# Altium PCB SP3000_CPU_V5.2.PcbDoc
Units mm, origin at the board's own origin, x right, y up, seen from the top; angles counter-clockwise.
Board outline 91.48 x 91.59 mm, 4 copper layers (Top Layer, PWR, GND, Bottom Layer); 84 components, 93 nets, 328 pads, 88 vias.
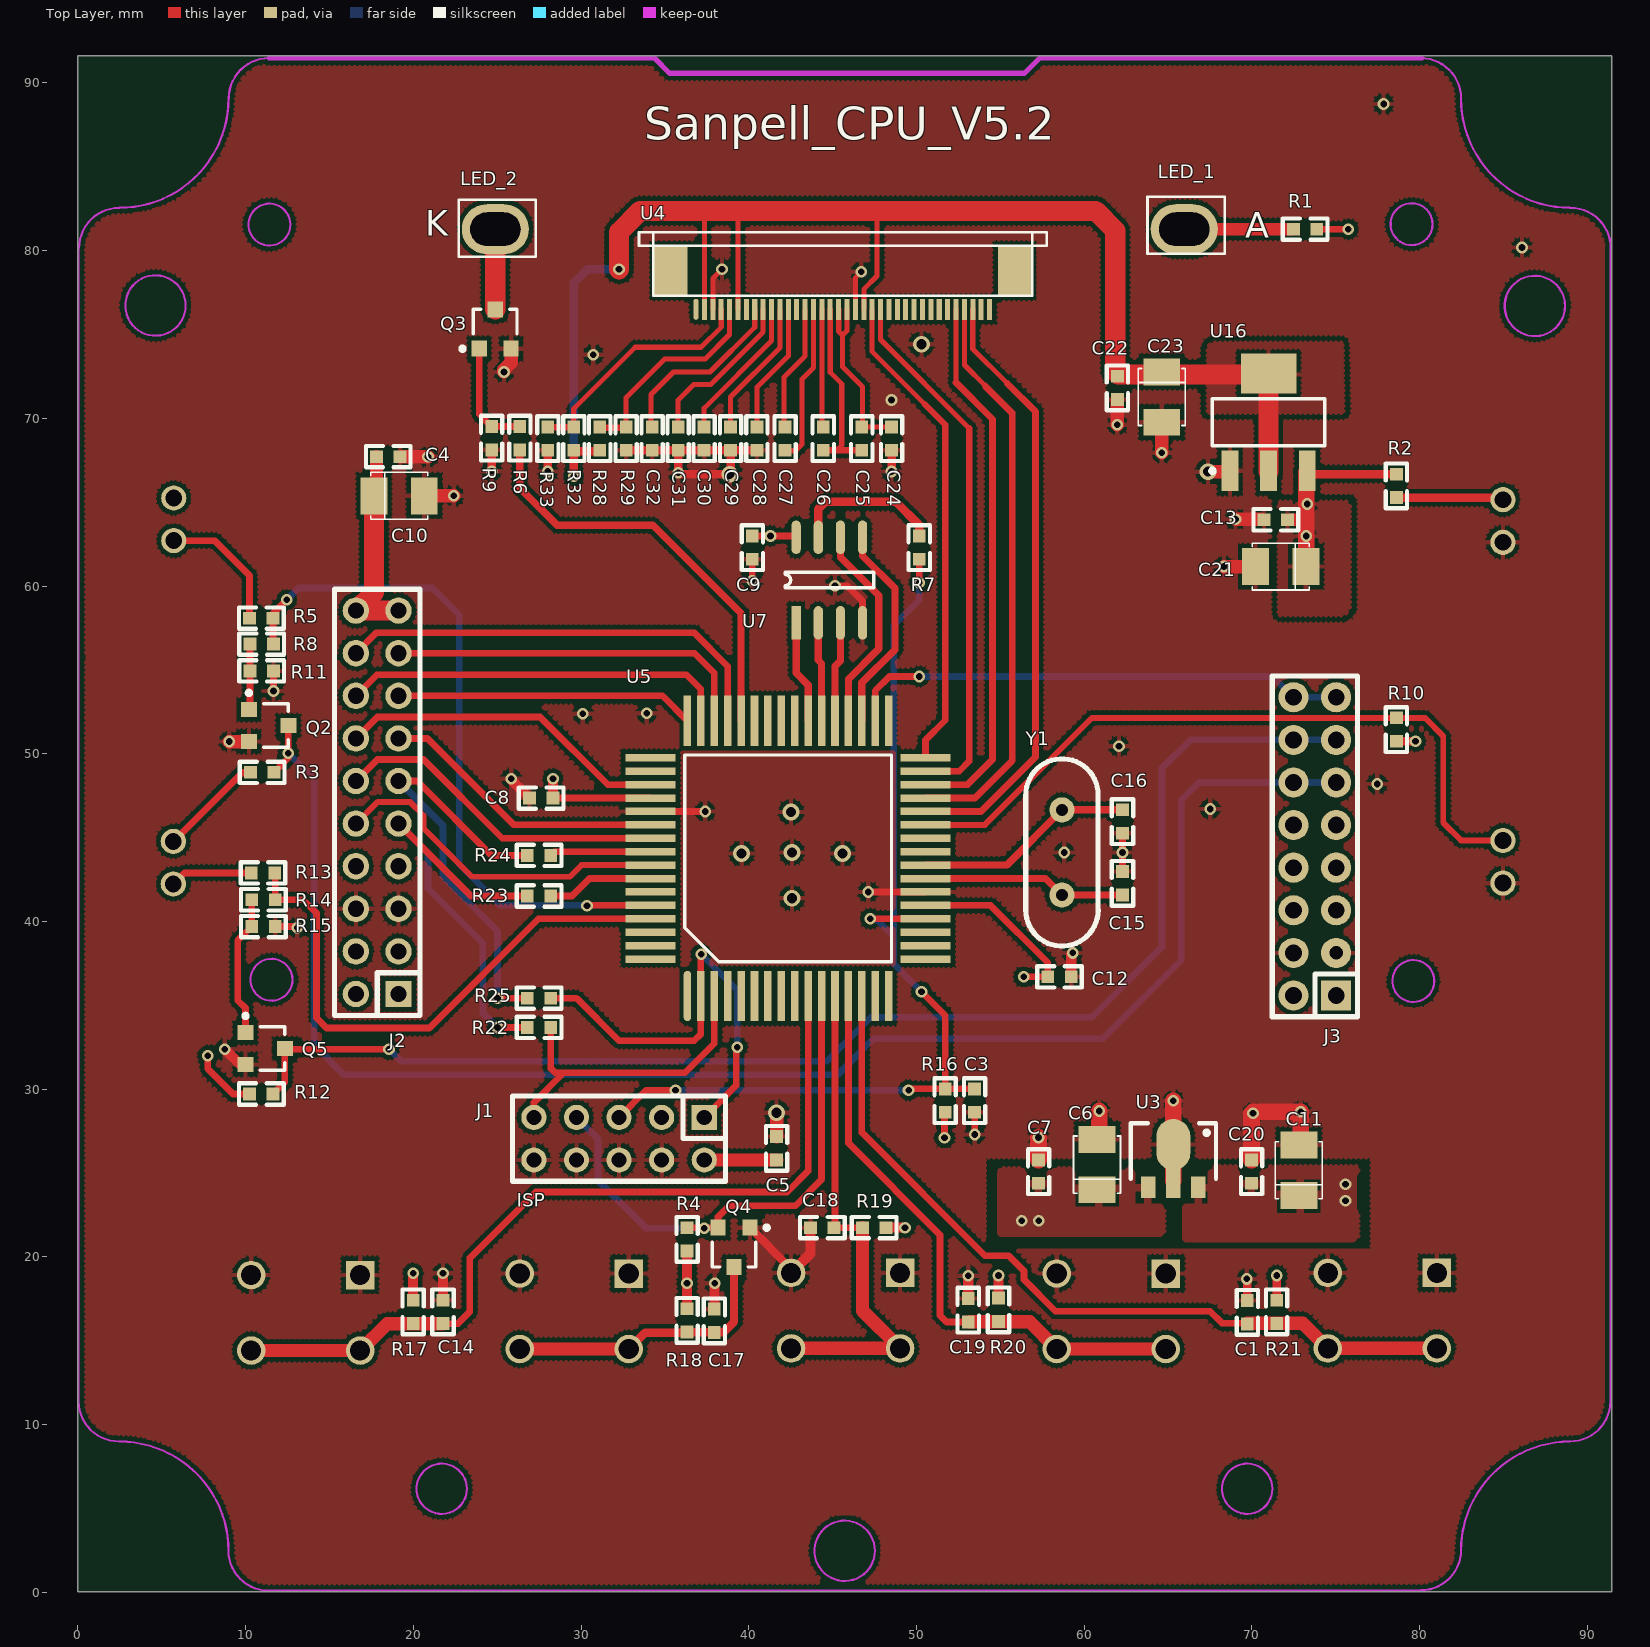
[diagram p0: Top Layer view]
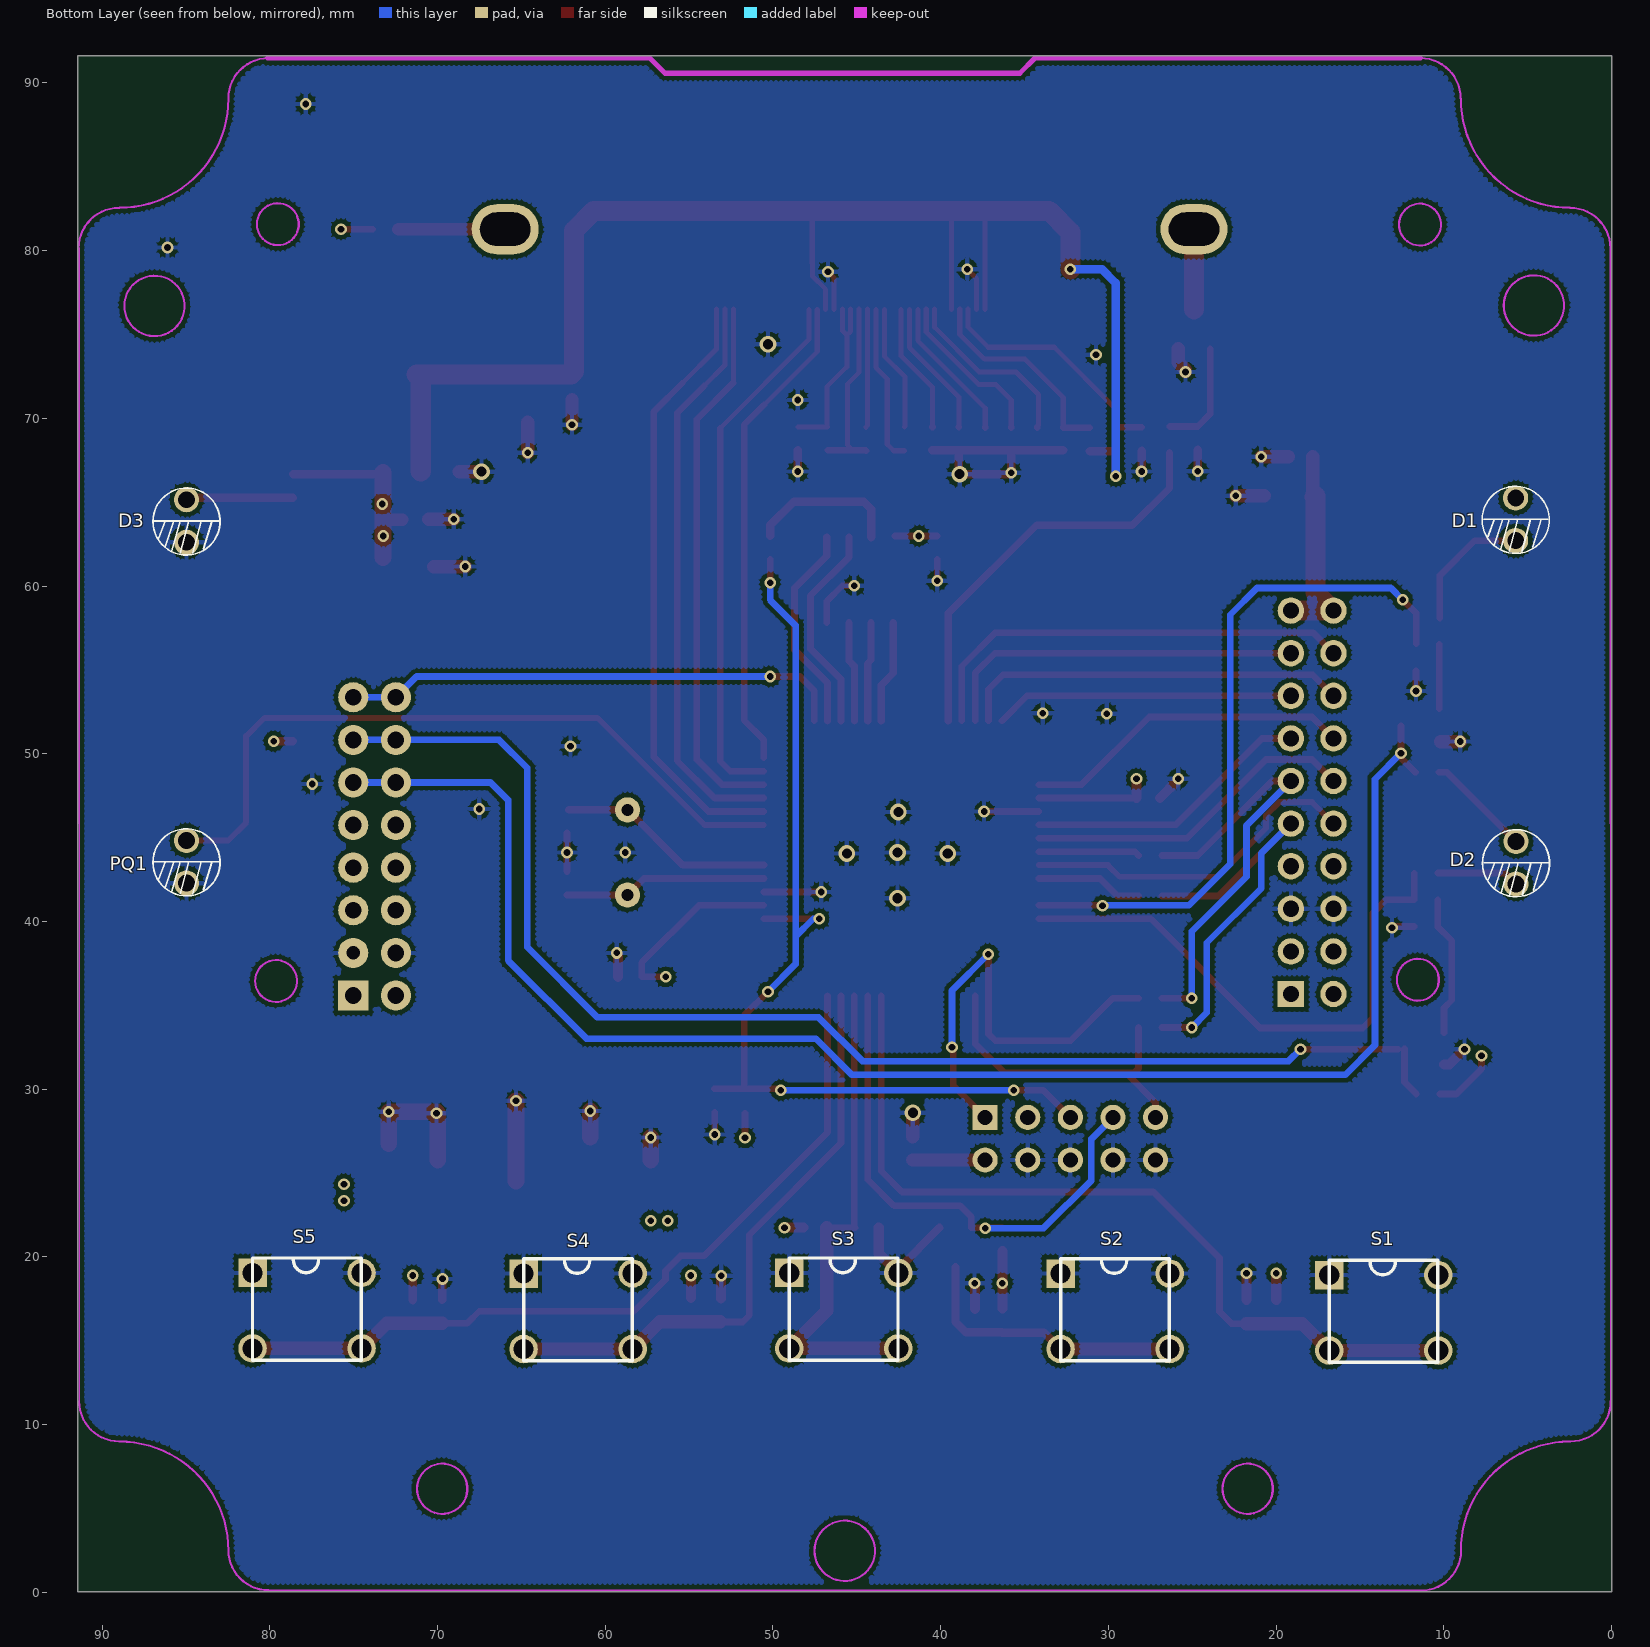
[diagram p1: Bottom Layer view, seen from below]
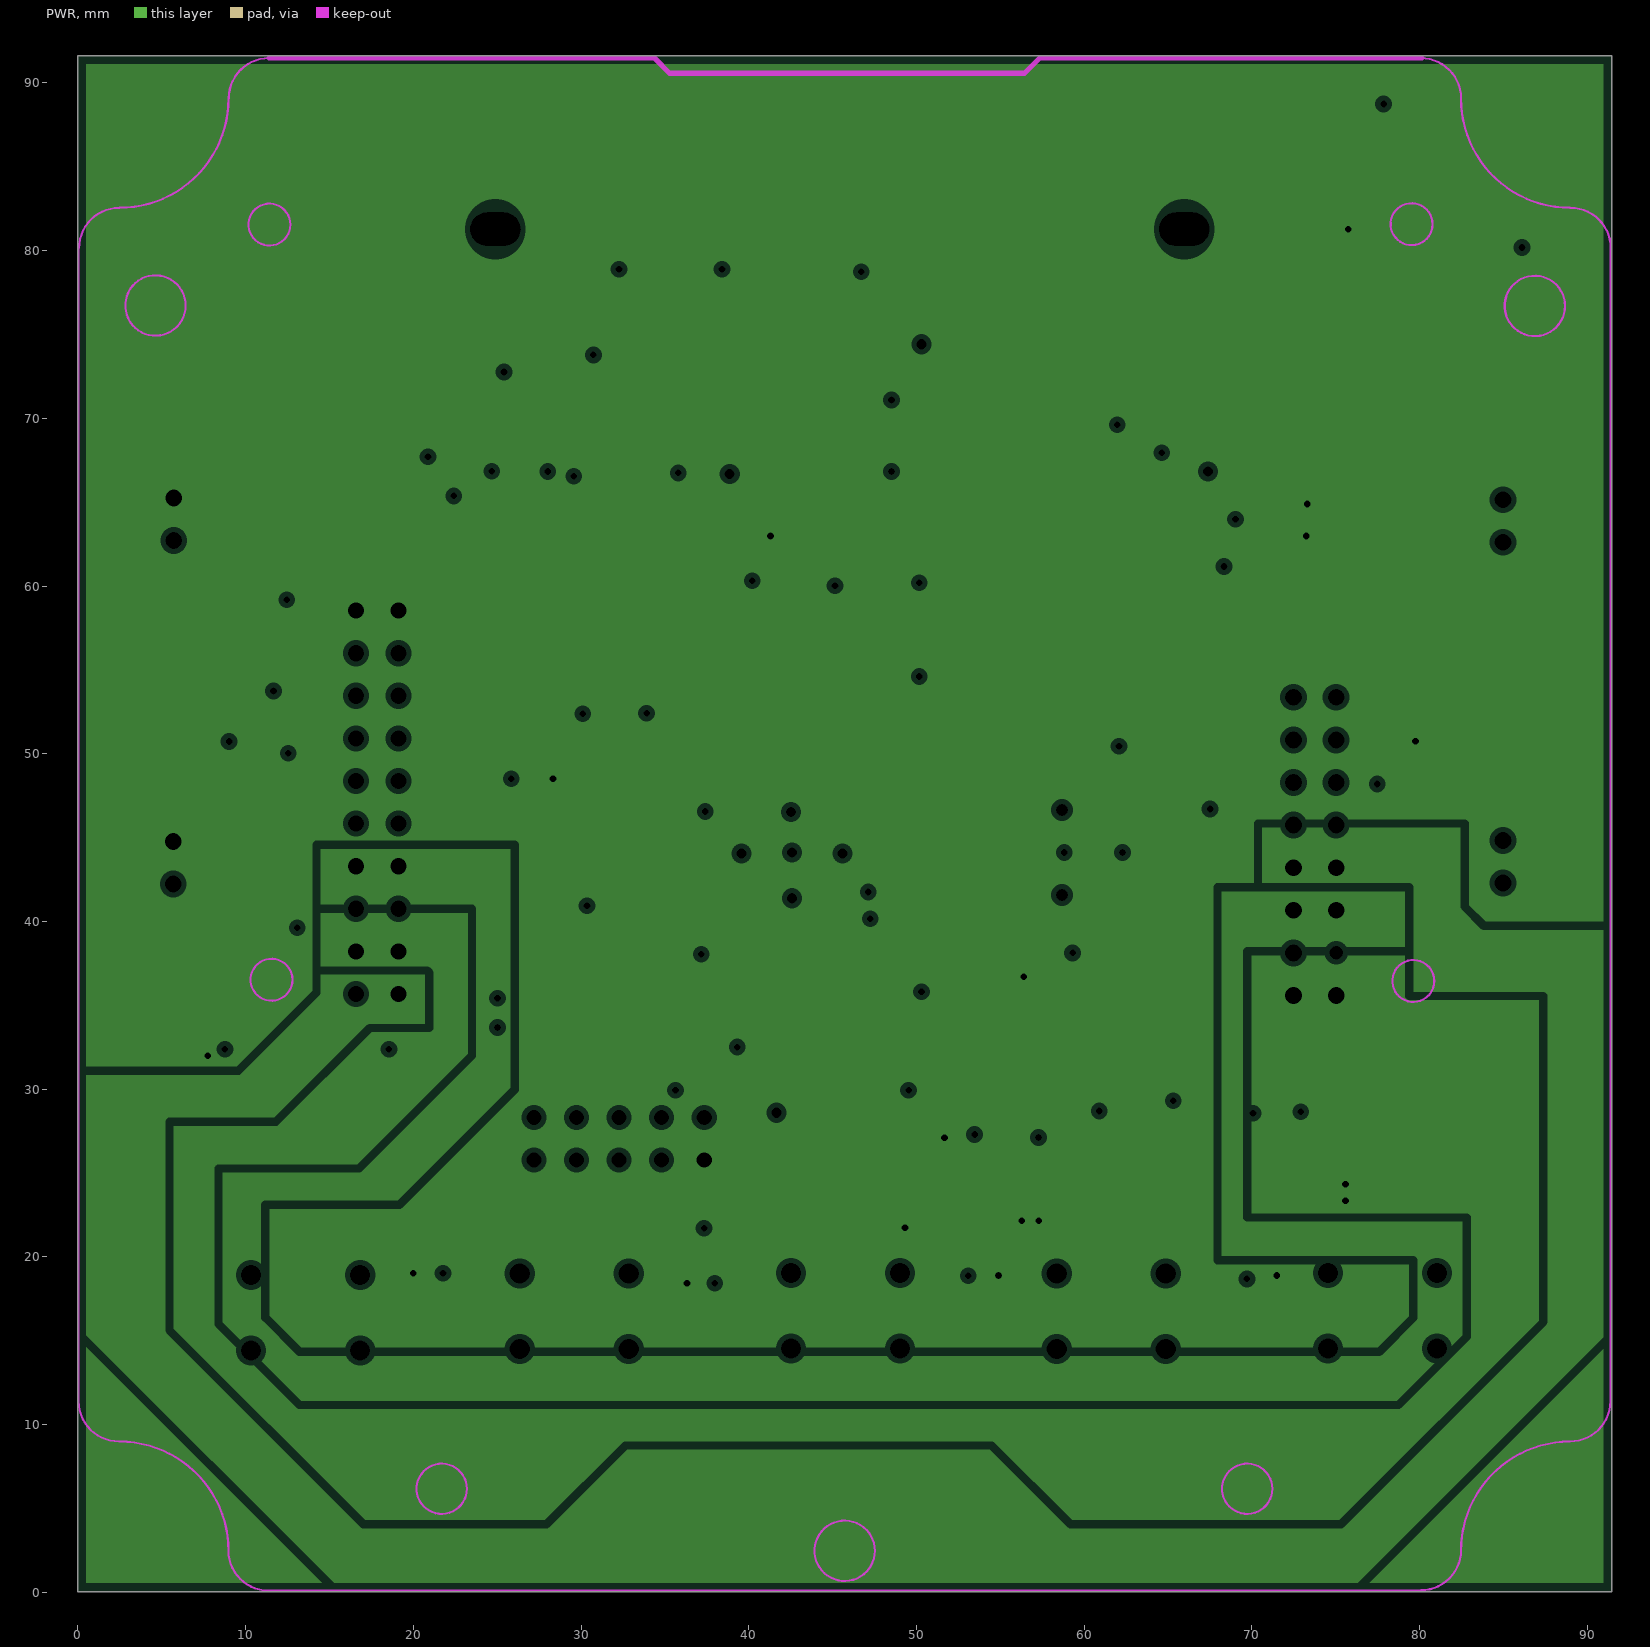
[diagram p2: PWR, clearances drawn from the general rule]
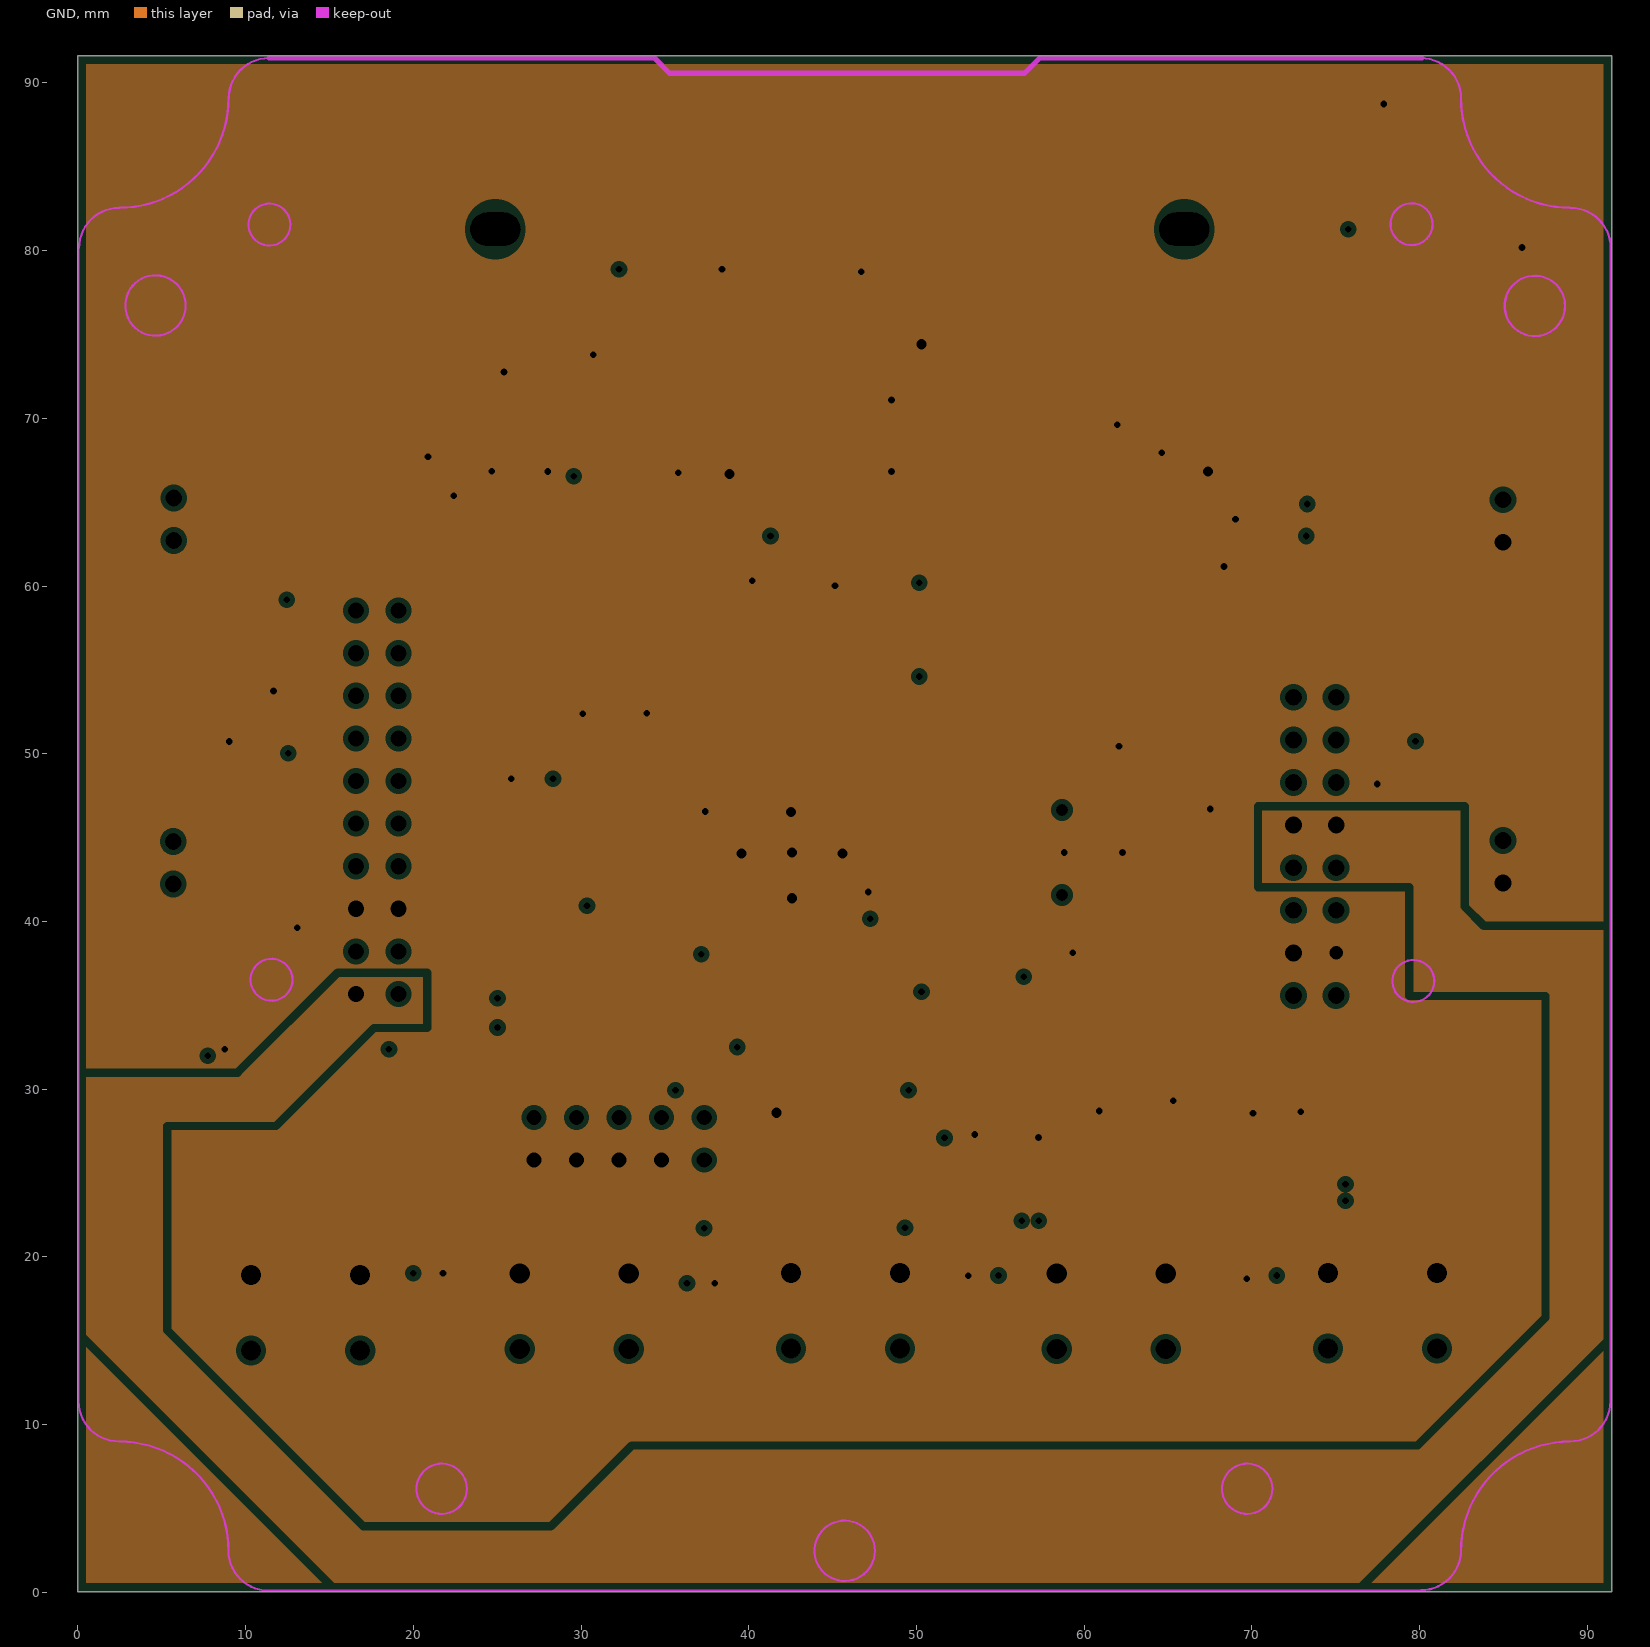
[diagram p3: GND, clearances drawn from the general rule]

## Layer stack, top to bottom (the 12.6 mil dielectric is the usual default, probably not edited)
Top Layer: signal copper 0.0356
Dielectric: prepreg 0.32, FR-4, Dk 4.8
PWR: plane copper 0.0356, net (Multiple Nets)
Dielectric: core 0.32, FR-4, Dk 4.8
GND: plane copper 0.0356, net (Multiple Nets)
Dielectric: prepreg 0.32, FR-4, Dk 4.8
Bottom Layer: signal copper 0.0356

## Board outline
-0.02,0.041 91.457,0.041 91.457,91.632 -0.02,91.632

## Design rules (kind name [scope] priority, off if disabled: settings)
Clearance Clearance_poly [InPolygon] p1: gap=0.254
Clearance [All] p2: gap=0.15
ComponentClearance [All] p1: gap=0 collisioncheckmode=3 verticalgap=0.254 showdistances=FALSE
HoleSize [All] p1: absolutevalues=TRUE maxlimit=5 minlimit=0.025 maxpercent=80.000 minpercent=20.000
HoleToHoleClearance [All] p1: gap=0.1 allowstackedmicrovias=TRUE
MinimumSolderMaskSliver [All] p1: minsoldermaskwidth=0
PlaneClearance [All] p1: clearance=0.3
PlaneConnect [All] p1: planeconnectstyle=Relief reliefexpansion=0.508 reliefentries=4 reliefconductorwidth=0.3 reliefairgap=0.3
PolygonConnect [All] p1: connectstyle=Relief reliefconductorwidth=0.254 reliefentries=4 polygonreliefangle="90 Angle"
RoutingPriority [All] p1: routingpriority=4
RoutingVias [All] p1: holewidth=0.4 width=0.5 viastyle="Through Hole" minholewidth=0.3 minwidth=0.5 maxholewidth=1 maxwidth=3
SilkToSilkClearance [All] p1: silktosilkclearance=0
SilkscreenOverComponentPads [All] p1: minsilkscreentomaskgap=0
SolderMaskExpansion [All] p1: expansion=0.102
Width [All] p1: maxlimit=5.08 minlimit=0.254 preferedwidth=0.254
19 further rules are at their usual default settings.

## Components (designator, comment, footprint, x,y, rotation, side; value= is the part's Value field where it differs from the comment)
C1 "0.1uF" 0603 69.723,17.399 r270 top
C3 "1uF" 0603 53.465,30.023 r270 top
C4 "0.1uF" 0603 19.202,67.716 r180 top
C5 "0.1uF" 0603 41.656,27.178 r270 top
C6 "10uF" B 60.765,24.009 r90 top
C7 "0.1uF" 0603 57.278,25.788 r270 top
C8 "0.1uF" 0603 26.924,47.364 r0 top
C9 "10uF" 0603 40.208,61.595 r90 top
C10 "10uF" B 17.653,65.38 r0 top
C11 "10uF" B 72.796,23.673 r90 top
C12 "0.1uF" 0603 59.225,36.703 r180 top
C13 "0.1uF" 0603 70.725,63.957 r0 top
C14 "0.1uF" 0603 21.768,17.424 r270 top
C15 "22P" 0603 62.281,42.977 r270 top
C16 "22P" 0603 62.281,46.66 r270 top
C17 "0.1uF" 0603 37.948,16.891 r270 top
C18 "0.1uF" 0603 43.688,21.75 r0 top
C19 "0.1uF" 0603 53.086,17.526 r270 top
C20 "0.1uF" 0603 69.978,24.391 r90 top
C21 "10uF" B 73.214,61.163 r180 top
C22 "0.1uF" 0603 61.976,72.517 r270 top
C23 "10uF" B 64.624,72.771 r270 top
C24 "0.1uF" 0603 48.514,69.494 r270 top
C25 "0.1uF" 0603 46.736,69.494 r270 top
C26 "0.1uF" 0603 44.439,69.494 r270 top
C27 "0.1uF" 0603 42.164,68.097 r90 top
C28 "0.1uF" 0603 40.488,69.494 r270 top
C29 "0.1uF" 0603 38.913,69.494 r270 top
C30 "0.1uF" 0603 37.338,69.494 r270 top
C31 "0.1uF" 0603 35.789,69.494 r270 top
C32 "0.1uF" 0603 34.239,69.494 r270 top
D1 "Led" LED 5.715,65.253 r270 bottom
D2 "Led" LED 5.69,44.78 r270 bottom
D3 "Led" LED 84.963,65.151 r270 bottom
J1 "ISP" IDC10 32.264,27.055 r180 top
J2 "HEADER 10X2" IDC20 19.116,35.68 r90 top
J3 "CON16" IDC16 73.751,44.482 r90 top
LED_1 "CON1" LEC_A#1 65.964,81.458 r0 top
LED_2 "CON1" LEC_A#2 24.892,81.28 r0 top
PQ1 "MI3-P" LED 84.963,44.831 r270 bottom
Q2 "Npn" 9013 11.37,51.682 r270 top
Q3 "G1" 9013 24.882,75.329 r0 top
Q4 "WNM2021-3/TR" 9013 39.116,20.574 r180 top
Q5 "Npn" 9013 11.166,32.423 r270 top
R1 "100K" 0603 73.868,81.28 r180 top
R2 "10K" 0603 78.613,66.675 r270 top
R3 "10K" 0603 11.684,48.895 r180 top
R4 "100K" 0603 36.322,21.749 r270 top
R5 "10K" 0603 11.633,58.09 r180 top
R6 "1K" 0603 26.346,69.52 r270 top
R7 "0R" 0603 50.165,61.595 r90 top
R8 "1K" 0603 11.659,56.54 r180 top
R9 "10K" 0603 24.67,68.123 r90 top
R10 "10K" 0603 78.613,52.146 r270 top
R11 "10K" 0603 11.659,54.94 r180 top
R12 "10K" 0603 11.633,29.718 r180 top
R13 "10K" 0603 11.735,42.901 r180 top
R14 "1K" 0603 11.76,41.3 r180 top
R15 "10K" 0603 11.76,39.7 r180 top
R16 "10K" 0603 51.708,30.023 r270 top
R17 "100K" 0603 19.99,16.027 r90 top
R18 "100K" 0603 36.322,15.519 r90 top
R19 "100K" 0603 46.78,21.75 r0 top
R20 "100K" 0603 54.889,16.154 r90 top
R21 "100K" 0603 71.476,16.027 r90 top
R22 "NC" 0603 26.797,33.687 r0 top
R23 "0R" 0603 26.797,41.522 r0 top
R24 "0R" 0603 26.797,43.942 r0 top
R25 "NC" 0603 26.797,35.433 r0 top
R28 "1K" 0603 31.115,68.097 r90 top
R29 "1k" 0603 32.69,68.097 r90 top
R32 "1k" 0603 29.566,68.097 r90 top
R33 "1K" 0603 28.016,68.097 r90 top
S1 "" SW3-DIP 16.83,18.923 r180 bottom
S2 "" SW3-DIP 32.846,19.013 r180 bottom
S3 "" SW3-DIP 49.022,19.05 r180 bottom
S4 "" SW3-DIP 64.864,19.013 r180 bottom
S5 "" SW3-DIP 81.026,19.05 r180 bottom
U3 "7805" 7805 66.81,24.162 r0 top
U4 "CON36" LCD_36 54.356,76.504 r270 top (schematic designator U4_1)
U5 "Atmega128" Quad64 42.342,43.383 r90 top
U7 "X5045" SOP8 42.824,57.81 r90 top
U16 "ASM1117_2" MP04A_N 70.993,69.771 r90 top
Y1 "8M" CY 58.674,44.12 r270 top

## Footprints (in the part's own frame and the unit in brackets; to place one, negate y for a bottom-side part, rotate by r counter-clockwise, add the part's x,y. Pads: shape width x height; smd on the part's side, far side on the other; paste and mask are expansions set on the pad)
0603 [mil]
  rect 30x30 smd: 1(0,0) 2(55,0)
  silkscreen extent -25,-25 80,25
7805 [mil]
  rect 34x50 smd: 1(0.08,-0.02) 3(-117.92,-0.02)
  rect 34x78.74 smd: 2(-58.92,13.98)
  oval 80x120 smd: 4(-58.92,99.98)
  silkscreen extent -159,20 41,150
9013 [mm]
  rect 0.9x0.95 smd: 1(-0.95,-1.175) 2(0.95,-1.175) 3(0,1.175)
  silkscreen extent -2.07,-1.3 1.3,1.18
B [mm]
  rect 1.6x2.2 smd: 1(0,0) 2(3,0)
  silkscreen extent -0.2,-1.4 3.2,1.4
CY [mm]
  round 1.5 hole 0.711: 1(-2.54,0) 2(2.54,0)
  silkscreen extent -5.58,-2.16 5.58,2.16
IDC10 [mm]
  rect 1.5x1.5 hole 0.9: 1(-5.08,-1.27)
  round 1.5 hole 0.9: 2(-5.08,1.27) 3(-2.54,-1.27) 4(-2.54,1.27) 5(0,-1.27) 6(0,1.27) 7(2.54,-1.27) 8(2.54,1.27) 9(5.08,-1.27) 10(5.08,1.27)
  silkscreen extent -6.35,-2.54 6.35,2.54
IDC16 [mm]
  rect 1.8x1.8 hole 1: 1(-8.89,-1.27)
  round 1.8 hole 1: 2(-8.89,1.27) 4(-6.35,1.27) 5(-3.81,-1.27) 6(-3.81,1.27) 7(-1.27,-1.27) 8(-1.27,1.27) 9(1.27,-1.27) 10(1.27,1.27) 11(3.81,-1.27) 12(3.81,1.27) 13(6.35,-1.27) 14(6.35,1.27) 15(8.89,-1.27) 16(8.89,1.27)
  round 1.8 hole 0.8: 3(-6.35,-1.27)
  silkscreen extent -10.16,-2.54 10.16,2.54
IDC20 [mil]
  rect 62x62 hole 38: 1(0,0)
  round 62 hole 38: 2(0,100) 3(100,0) 4(100,100) 5(200,0) 6(200,100) 7(300,0) 8(300,100) 9(400,0) 10(400,100) 11(500,0) 12(500,100) 13(600,0) 14(600,100) 15(700,0) 16(700,100) 17(800,0) 18(800,100) 19(900,0) 20(900,100)
  silkscreen extent -50,-50 950,150
LCD_36 [mm]
  rect 1.25x0.3 smd: 1(0,0) 2(0,-0.5) 3(0,-1) 4(0,-1.5) 5(0,-2) 6(0,-2.5) 7(0,-3) 8(0,-3.5) 9(0,-4) 10(0,-4.5) 11(0,-5) 12(0,-5.5) 13(0,-6) 14(0,-6.5) 15(0,-7) 16(0,-7.5) 17(0,-8) 18(0,-8.5) 19(0,-9) 20(0,-9.5) 21(0,-10) 22(0,-10.5) 23(0,-11) 24(0,-11.5) 25(0,-12) 26(0,-12.5) 27(0,-13) 28(0,-13.5) 29(0,-14) 30(0,-14.5) 31(0,-15) 32(0,-15.5) 33(0,-16) 34(0,-16.5) 35(0,-17)
  oval 1.25x0.3 smd: 36(0,-17.5)
  rect 3x2 smd: 37(-2.3,1.5) 38(-2.3,-19)
  silkscreen extent -4.6,-20.9 -0.8,3.4
LEC_A#1 [mm]
  oval 4x3 hole 2 slot 3 at 0 deg: 1(0,-0.178)
  silkscreen extent -2.19,-1.64 2.41,1.76
LEC_A#2 [mm]
  oval 4x3 hole 2 slot 3 at 0 deg: 1(0,0)
  silkscreen extent -2.19,-1.64 2.41,1.76
LED [mm]
  round 1.5 hole 1: 1(0,0) 2(2.54,0)
  silkscreen extent -0.7,-2 3.3,2
MP04A_N [mm] "SOT223, 4-Leads, Body 6.5x3.5mm, Pitch 2.3mm, Lead Span 7mm, IPC Medium Density"
  rect 2.4x1 smd: 1(-2.9,-2.3) 2(-2.9,0) 3(-2.9,2.3)
  rect 2.4x3.3 smd: 4(2.9,0)
  silkscreen extent -3.02,-3.35 1.4,3.47, body extent -1.85,-3.35 1.85,3.35, height 1.8
Quad64 [mm]
  oval 3x0.45 smd: 1(-7.819,6)
  rect 3x0.45 smd: 2(-7.819,5.2) 3(-7.819,4.4) 4(-7.819,3.6) 5(-7.819,2.8) 6(-7.819,2) 7(-7.819,1.2) 8(-7.819,0.4) 9(-7.819,-0.4) 10(-7.819,-1.2) 11(-7.819,-2) 12(-7.819,-2.8) 13(-7.819,-3.6) 14(-7.819,-4.4) 15(-7.819,-5.2) 16(-7.819,-6) 33(8.581,-6) 34(8.581,-5.2) 35(8.581,-4.4) 36(8.581,-3.6) 37(8.581,-2.8) 38(8.581,-2) 39(8.581,-1.2) 40(8.581,-0.4) 41(8.581,0.4) 42(8.581,1.2) 43(8.581,2) 44(8.581,2.8) 45(8.581,3.6) 46(8.581,4.4) 47(8.581,5.2) 48(8.581,6)
  rect 0.45x3 smd: 17(-5.619,-8.2) 18(-4.819,-8.2) 19(-4.019,-8.2) 20(-3.219,-8.2) 21(-2.419,-8.2) 22(-1.619,-8.2) 23(-0.819,-8.2) 24(-0.019,-8.2) 25(0.781,-8.2) 26(1.581,-8.2) 27(2.381,-8.2) 28(3.181,-8.2) 29(3.981,-8.2) 30(4.781,-8.2) 31(5.581,-8.2) 32(6.381,-8.2) 49(6.381,8.2) 50(5.581,8.2) 51(4.781,8.2) 52(3.981,8.2) 53(3.181,8.2) 54(2.381,8.2) 55(1.581,8.2) 56(0.781,8.2) 57(-0.019,8.2) 58(-0.819,8.2) 59(-1.619,8.2) 60(-2.419,8.2) 61(-3.219,8.2) 62(-4.019,8.2) 63(-4.819,8.2) 64(-5.619,8.2)
  silkscreen extent -5.78,-6.16 6.55,6.17
SOP8 [mm]
  rect 2x0.55 smd: 1(0,0)
  oval 2x0.55 smd: 2(0,-1.32) 3(0,-2.64) 4(0,-3.96) 5(5.1,-3.96) 6(5.1,-2.64) 7(5.1,-1.32) 8(5.1,0)
  silkscreen extent 2.08,-4.62 3.01,0.66
SW3-DIP [mm]
  rect 1.7x1.7 hole 1.2: 1(0,0)
  round 1.7 hole 1.2: 1(6.5,0) 2(0,-4.5) 2(6.5,-4.5)
  silkscreen extent 0,-5.21 6.48,0.89

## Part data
C1 C3 C4 C5 C6 C7 C8 C9 C10 C11 C12 C13 C14 C15 C16 C17 C18 C19 C20 C21 C22 C23: library part Cap, "C?"
C24 C25 C26 C27 C28 C29 C30 C31 C32: library part CAP, "Capacitor"
D1 D2 D3: "D?"
J1: library part isp, "U?"
J3 LED_1 LED_2 U4: "Connector"
PQ1: library part Led, "D?"
Q2 Q5: "Q?"
Q3: library part Npn, "Q?"
Q4: library part "Header 3", "N-Channel, 20V, 0.89A, Small Signal MOSFET"
R1 R2 R3 R4 R5 R6 R7 R8 R9 R10 R11 R12 R13 R14 R15 R16 R17 R18 R19 R20 R21 R22 R23 R24 R25 R28 R29 R32 R33: library part Res, "R?"
S1 S2 S3 S4 S5: library part Sw-pb, "S?"
U3: "U"
U5: "U?"
Y1: library part Xtal, "Y?"

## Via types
v1: diameter 0.7, hole 0.4, Top Layer to Bottom Layer, 79 vias
v2: diameter 1, hole 0.6, Top Layer to Bottom Layer, 9 vias

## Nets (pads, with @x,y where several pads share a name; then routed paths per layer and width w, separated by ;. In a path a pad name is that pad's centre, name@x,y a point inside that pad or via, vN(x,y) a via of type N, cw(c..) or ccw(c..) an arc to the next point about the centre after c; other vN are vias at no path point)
+12V: C11.1 C20.1 J2.3 J2.4 J3.1 J3.2 U3.1
  other v1: 75.573,23.349 75.573,24.34
+24V: J2.1 J3.7 J3.8
-12V: J2.7 J2.8 J3.5 J3.6
C1N: C25.2 C26.2 U4.20 | length 11.1
  Top Layer w0.305: U4.20 44.856,72.746 45.542,72.06 45.542,70.561 45.542,68.402 45.237,68.097
  Top Layer w0.4: C26.2@44.439,68.072 44.465,68.097 45.237,68.097 C25.2
C1P: C26.1 U4.21 | length 7.1
  Top Layer w0.305: U4.21 44.356,69.578 C26.1 C26.1@44.439,69.469
C2N: C27.2 U4.23 | length 7.5
  Top Layer w0.3: C27.2 42.113,69.545 42.113,72.466 43.356,73.709 U4.23
C2P: C27.1 U4.22 | length 9.5
  Top Layer w0.3: 43.18,72.351 43.856,73.027 U4.22
  Top Layer w0.305: C27.1@42.164,68.072 42.799,68.072 43.18,68.453 43.18,72.351
CS-CS: J2.16 U5.47 | length 23.3
  Top Layer w0.4: J2.16 17.828,54.712 36.278,54.712 37.142,53.848 U5.47
CS-SCK: J2.15 U5.48 | length 17.8
  Top Layer w0.4: J2.15 34.846,53.46 U5.48
CS-SDI: J2.17 U5.46 | length 22.2
  Top Layer w0.4: J2.17 36.761,56 37.942,54.819 U5.46
CS-SDO: J2.18 U5.45 | length 26.8
  Top Layer w0.4: J2.18 17.802,57.226 36.735,57.226 38.742,55.22 U5.45
D0: 
D1: 
D2: 
D3: 
D4: 
D5: 
GND: C1.1 C3.2 C4.1 C5.1 C6.2 C7.1 C8.1 C9.1 C10.2 C11.2 C12.1 C13.1 C14.1 C15.1 C16.2 C17.1 C18.1 C19.1 C20.2 C21.2 C22.2 C23.2 C24.2 C28.2 C29.2 C30.2 C31.2 C32.2 D3.2 J1.4 J1.6 J1.8 J1.10 J2.5 J2.6 J3.3 J3.4 PQ1.2 Q2.2 Q3.2 Q4.1 Q5.2 R9.1 R11.1 R15.1 R29.1 R33.1 S1.1 S2.1 S3.1 S4.1 S5.1 U3.2 U3.4 U4.17 U4.34 U5.22 U5.53 U7.4 U16.3 | length 88.1
  Top Layer w0.3: U4.34 37.856,78.344 v1(38.405,78.892) ; U4.17 46.356,78.385 v1(46.711,78.74)
  Top Layer w0.4: v1(11.659,53.746) R11.1 ; R15.1 13.005,39.7 v1(13.081,39.624) ; v1@25.838,48.45 v1(25.838,48.514) ; U5.53 v1(37.407,46.564) ; v1(40.208,60.325) C9.1 ; v1(45.142,60.02) 45.866,60.02 46.784,59.101 U7.4 ; v1(47.117,41.764) U5.22 ; v1(53.465,27.305) C3.2
  Top Layer w0.432: C15.1 v1(62.281,44.12) C16.2
  Top Layer w0.5: v1(24.67,66.855) R9.1 ; Q4.1 42.522,19.293 S3.1@42.522,19.05 ; v1(48.514,66.827) C24.2
  Top Layer w0.508: v1(22.403,65.38) v1@22.428,65.38 ; v1(28.016,66.827) R33.1@28.016,68.072 ; R29.1 C32.2 C31.2 ; C28.2 C29.2 ; C1.1@69.723,17.45 v1@69.723,18.669 ; C31.2 C30.2 C29.2 ; C31.2 v1(35.789,66.751) 35.865,66.675 v2(38.862,66.675) 38.913,66.675 C29.2
  Top Layer w0.6: v1(8.763,32.385) 9.675,31.473 Q5.2 ; C14.1 v1@21.768,18.948 ; v1@25.838,48.45 C8.1 ; C17.1 v1@37.948,18.429 ; S3.1@42.522,19.05 43.688,20.216 C18.1 ; C19.1 v1(53.086,18.886) ; C12.1 59.225,38.048 v1(59.309,38.132)
  Top Layer w0.8: v1(9.017,50.732) Q2.2 ; C4.1@19.256,67.716 v1(20.879,67.716) ; C10.2@20.701,65.38 v1(22.403,65.38) ; v1(25.4,72.771) 25.4,72.898 25.832,73.33 Q3.2 ; C5.1 v2(41.656,28.6) ; v1(61.976,69.621) C22.2 ; v1(64.624,67.945) C23.2 ; v2(67.377,66.823) U16.3@68.693,66.823 ; v1(68.337,61.163) C21.2 ; v1(69.023,63.983) C13.1@70.522,63.983
  Top Layer w1: C7.1 v1(57.278,27.127) ; C6.2@60.892,27.136 v1(60.892,28.708) ; U3.2 U3.4 v1(65.313,29.316) ; C20.2 v1@69.978,28.575 ; v1@70.061,28.658 v1(72.906,28.658) C11.2@72.906,26.755
  Bottom Layer w0.4: v1(46.711,78.74) v1@46.839,78.611
  other v1: 37.973,18.429 69.698,18.694 21.768,19.025 70.061,28.575 58.807,44.12 67.507,46.708 77.47,48.198 62.069,50.451 30.099,52.393 33.909,52.42 48.514,71.095 30.734,73.787 86.1,80.184 77.851,88.751
  other v2: 42.571,41.39 39.573,44.051 45.593,44.051 42.571,44.12 42.522,46.538 50.292,74.422
JXL-A0: U4.5 U5.30 | length 32.4
  Top Layer w0.305: 52.356,72.129 U4.5
  Top Layer w0.4: U5.30 53.041,48.164 54.534,49.657 54.534,69.952 52.356,72.129
JXL-CS: U4.3 U5.28 | length 36.1
  Top Layer w0.305: U4.3 53.356,74.143 55.405,72.093
  Top Layer w0.4: U5.28 53.85,46.564 57.099,49.813 57.099,70.399 55.405,72.093
JXL-RST: U4.4 U5.29 | length 34.2
  Top Layer w0.305: U4.4 52.856,73.179 54.093,71.942
  Top Layer w0.4: U5.29 53.486,47.364 55.702,49.581 55.702,70.333 54.093,71.942
JXL-SCK: U4.14 U5.31 | length 32
  Top Layer w0.3: 47.856,74.699 U4.14
  Top Layer w0.305: 47.856,74.699 53.137,69.418
  Top Layer w0.4: U5.31 52.546,48.964 53.137,49.555 53.137,69.418
JXL-SDA: U4.15 U5.32 | length 29.1
  Top Layer w0.3: 47.356,73.98 U4.15
  Top Layer w0.305: 47.356,73.98 50.521,70.815 50.546,70.815
  Top Layer w0.4: 50.521,70.815 51.714,69.621 51.714,52.002 50.538,50.825 50.542,50.821 U5.32
LEDK: LED_2.1 Q3.3 | length 4.7
  Top Layer w1.2: Q3.3 LED_2.1@24.882,81.168
LIN: PQ1.1 R10.1 U5.27 | length 43.1
  Top Layer w0.35: U5.27 54.077,45.764 60.459,52.147 R10.1 80.315,52.146 81.407,51.054 81.407,45.898 82.474,44.831 PQ1.1
MANU-LED: R6.2 U5.44 | length 24.8
  Top Layer w0.432: R6.2@26.346,67.945 26.346,65.856 28.575,63.627 34.29,63.627 39.542,58.375 U5.44
MISO: J1.9 R22.2 U5.3 | length 19.2
  Top Layer w0.4: J1.9 27.184,29.216 28.956,30.988 36.195,30.988 37.942,32.735 U5.3
  Top Layer w0.406: R22.2 28.194,31.242 28.448,30.988 28.956,30.988
MISO1: J2.9 R22.1 R23.1 | length 25.8
  Top Layer w0.4: J2.9 23.434,41.522 R23.1 ; v1(25.019,33.687) R22.1
  Bottom Layer w0.4: J2.9 20.879,44.077 20.879,41.986 24.13,38.735 24.13,34.576 v1(25.019,33.687)
MOSI: J1.1 R25.2 U5.2 | length 26.4
  Top Layer w0.4: R25.2 29.718,35.433 32.258,32.893 36.734,32.893 37.142,33.301 U5.2 37.142,38.031 v1(37.16,38.049) ; J1.1 39.249,30.23 39.249,32.442 v1(39.319,32.512)
  Bottom Layer w0.4: v1(37.16,38.049) 39.319,35.89 v1(39.319,32.512)
MOSI1: J2.12 U5.55 | length 20
  Top Layer w0.4: J2.12 17.853,49.657 20.606,49.657 25.298,44.964 U5.55
NC01: R28.2 R29.2 U4.32 | length 12.6
  Top Layer w0.305: R29.2 32.69,71.247 34.976,73.533 37.389,73.533 38.856,75 U4.32
  Top Layer w0.4: R28.2@31.115,69.444 32.69,69.444 R29.2
NetC17_2: C17.2 Q4.3 R18.1 S2.2 | length 16.7
  Top Layer w0.5: S2.2@32.846,14.513 33.827,15.494 R18.1@36.322,15.494 ; R18.1 38.506,15.519 39.116,16.129 Q4.3
  Top Layer w0.8: S2.2@26.346,14.513 S2.2@32.846,14.513
NetD1_2: D1.2 R5.2 | length 7.9
  Top Layer w0.4: D1.2 8.153,62.713 10.236,60.63 R5.2
NetD2_2: D2.2 R13.2 | length 4.9
  Top Layer w0.406: D2.2 6.35,42.901 R13.2
NetD3_1: D3.1 R2.2 | length 6.4
  Top Layer w0.5: R2.2 84.836,65.278 D3.1
  Top Layer w0.6: D3.1 D3.1@84.988,65.176
NetLED_1_1: LED_1.1 R1.2 | length 6.4
  Top Layer w0.762: LED_1.1 R1.2@72.344,81.28
NetQ2_1: Q2.1 R8.2 R11.2 | length 3.8
  Top Layer w0.4: Q2.1@10.262,52.699 R8.2
NetQ3_1: Q3.1 R6.1 R9.2 | length 6.6
  Top Layer w0.4: Q3.1 23.932,70.258 R9.2 R6.1
NetQ5_1: Q5.1 R14.2 R15.2 | length 8.5
  Top Layer w0.4: Q5.1 9.991,34.84 9.525,35.306 9.525,38.862 R15.2 R14.2
NetR7_2: R7.2 U7.7 | length 9.1
  Top Layer w0.508: U7.7 44.144,64.591 44.577,65.024 48.768,65.024 50.165,63.627 R7.2
OUT-HIGH: J3.11 J3.12 Q2.3 R3.1 | length 95.7
  Top Layer w0.4: R3.1 12.545,49.756 v1(12.545,50.038) Q2.3
  Bottom Layer w0.4: v1(12.545,50.038) 14.097,48.486 14.097,32.639 15.875,30.861 45.288,30.861 47.447,33.02 61.122,33.02 65.786,37.684 65.786,47.244 66.834,48.292 J3.12 J3.11
OUT-LOW: J3.13 J3.14 Q5.3 R12.1 | length 79.8
  Top Layer w0.4: R12.1 12.341,30.426 Q5.3 ; Q5.3@12.722,32.385 v1(18.542,32.385)
  Bottom Layer w0.4: v1(18.542,32.385) 19.253,31.674 44.653,31.674 47.269,34.29 60.452,34.29 64.643,38.481 64.643,49.149 66.326,50.832 J3.14 J3.13
OUT_CLEAR: J3.15 J3.16 U5.34 | length 30.2
  Top Layer w0.4: U5.34 47.542,53.765 48.387,54.61 v1(50.165,54.61) ; J3.16@72.471,53.372 J3.16
  Bottom Layer w0.4: v1(50.165,54.61) 71.243,54.61 J3.16 J3.15
PA1: U5.50
PA2: U5.49
PB5: U5.15
PB6: U5.16
PB7: U5.17
PC5: U5.40
PC6: U5.41
PC7: U5.42
PD0: U5.25
PD1: U5.26
PE3: U5.5
PE4: U5.6
PE5: U5.7
PE6: U5.8
PE7: U5.9
PF0: R13.1 R14.1 U5.61 | length 33.5
  Top Layer w0.4: R13.1@11.76,42.875 R14.1 13.437,41.3 14.224,40.513 14.224,34.262 14.831,33.655 20.955,33.655 27.464,40.164 U5.61
PF1: R5.1 R8.1 U5.60 | length 41.5
  Top Layer w0.4: R8.1@11.633,56.566 R5.1 11.633,58.369 v1(12.446,59.182) ; v1(30.353,40.945) 30.334,40.964 U5.60
  Bottom Layer w0.4: v1(12.446,59.182) 13.157,59.893 21.133,59.893 22.733,58.293 22.733,43.434 25.203,40.964 v1@30.353,40.964
PF2: U5.59
PF3: R23.2 U5.58 | length 6.4
  Top Layer w0.4: R23.2 29.457,41.522 30.499,42.564 U5.58
PF4: J2.10 U5.57 | length 20.7
  Top Layer w0.35: J2.10 17.853,47.117 19.812,47.117 20.606,46.323 20.606,45.561 23.495,42.672 29.337,42.672 30.029,43.364 U5.57
PF5: R24.2 U5.56 | length 6
  Top Layer w0.4: R24.2 28.416,44.164 U5.56
PS: R32.2 R33.2 U4.33 | length 14.5
  Top Layer w0.305: R32.2@29.566,69.52 29.566,70.581 33.227,74.242 37.158,74.242 38.356,75.44 U4.33
  Top Layer w0.4: R33.2@28.016,69.469 R32.2@29.566,69.469
RD: 
RST#: C3.1 J1.5 R7.1 R16.1 U5.20 | length 60.5
  Top Layer w0.4: J1.5 33.886,29.947 v1(35.636,29.947) ; v1(47.244,40.164) U5.20 ; v1(49.53,29.947) 49.606,30.023 R16.1@51.714,30.023 ; v1(50.165,60.198) R7.1 ; v1(50.292,35.814) 51.714,34.392 R16.1@51.714,30.023 ; C3.1@53.486,30.023 R16.1@51.714,30.023
  Bottom Layer w0.4: v1@35.687,29.947 v1(49.53,29.947) ; v1(47.244,40.164) 47.593,40.164 48.641,39.116 ; v1(50.165,60.198) 50.165,59.182 48.641,57.658 48.641,39.116 ; v1(50.292,35.814) 48.641,37.465 48.641,39.116
S1: C14.2 R17.1 S1.2 U5.10 | length 50
  Top Layer w0.4: C14.2 22.657,16.027 23.368,16.739 23.368,19.939 27.305,23.876 42.291,23.876 43.542,25.127 U5.10
  Top Layer w0.8: S1.2@10.33,14.423 16.83,14.423 18.434,16.027 R17.1 C14.2
S2: J1.7 Q4.2 R4.1 U5.11 | length 32.3
  Top Layer w0.4: R4.1 Q4.2 38.166,22.396 38.821,23.051 42.769,23.051 44.342,24.624 U5.11
  Bottom Layer w0.4: J1.7 31.013,27.035 31.013,24.566 33.862,21.717 v1(37.338,21.717)
S3: C18.2 R19.1 S3.2 U5.12 | length 30.1
  Top Layer w0.4: C18.2 C18.2@45.142,21.75 ; U5.12 C18.2@45.142,21.75 ; R19.1 C18.2@45.142,21.75
  Top Layer w0.8: S3.2@42.522,14.55 49.022,14.55 46.78,16.792 R19.1
S4: C19.2 R20.1 S4.2 U5.13 | length 35.5
  Top Layer w0.4: U5.13 45.942,26.787 51.407,21.322 51.407,16.519 51.797,16.129 C19.2
  Top Layer w0.8: C19.2@53.137,16.129 56.748,16.129 58.364,14.513 S4.2@64.864,14.513
S5: C1.2 R21.1 S5.2 U5.14 | length 48.1
  Top Layer w0.4: U5.14 46.742,27.426 54.102,20.066 55.507,20.066 56.407,19.166 56.407,18.65 58.293,16.764 67.508,16.764 68.219,16.053 C1.2@69.723,16.053
  Top Layer w0.508: R21.1 R21.1@71.501,16.053
  Top Layer w0.8: C1.2@69.723,16.053 71.501,16.053 73.023,16.053 74.526,14.55 S5.2@81.026,14.55
SCK1: J2.11 R24.1 R25.1 | length 26.7
  Top Layer w0.4: J2.11 20.232,48.38 24.67,43.942 R24.1 ; v1(25.019,35.433) R25.1
  Bottom Layer w0.4: J2.11 21.768,45.728 21.768,42.672 25.019,39.421 v1(25.019,35.433)
SEL0: J2.13 U5.54 | length 17.2
  Top Layer w0.4: J2.13 20.835,50.92 25.991,45.764 U5.54
SEL1: J2.14 U5.51 | length 19.8
  Top Layer w0.4: J2.14 17.853,52.197 27.559,52.197 31.592,48.164 U5.51
V0: C32.1 U4.29 | length 10.9
  Top Layer w0.305: C32.1 34.163,69.571 34.163,71.425 35.509,72.771 37.694,72.771 40.356,75.433 U4.29
  Top Layer w0.4: C32.1@34.239,69.444 C32.1
V1: C31.1 U4.28 | length 9.8
  Top Layer w0.305: C31.1 35.789,71.095 36.703,72.009 37.719,72.009 40.856,75.146 U4.28
  Top Layer w0.4: C31.1@35.789,69.444 C31.1
V2: C30.1 U4.27 | length 8.7
  Top Layer w0.3: C30.1 37.338,70.612 41.356,74.63 U4.27
  Top Layer w0.4: C30.1@37.338,69.444 C30.1
V3: C29.1 U4.26 | length 8.3
  Top Layer w0.3: C29.1 38.913,71.273 41.856,74.216 U4.26
  Top Layer w0.4: C29.1@38.913,69.469 C29.1
V4: C28.1 U4.25 | length 7.8
  Top Layer w0.3: C28.1 40.488,71.857 42.356,73.725 U4.25
  Top Layer w0.4: C28.1@40.488,69.469 C28.1
VCC: C4.2 C5.2 C6.1 C7.2 C8.2 C9.2 C10.1 C12.2 C13.2 C21.1 D1.1 D2.1 J1.2 J2.19 J2.20 R1.1 R2.1 R3.2 R4.2 R10.2 R12.2 R16.2 R17.2 R18.2 R19.2 R20.2 R21.2 U3.3 U5.21 U5.52 U7.8 U16.1 | length 72
  Top Layer w0.4: D2.1 9.804,48.895 R3.2 ; v1(7.747,32.004) 7.747,31.217 9.246,29.718 R12.2 ; C8.2@28.448,47.364 U5.52 ; C9.2 v1(41.3,62.992) U7.8@42.743,62.992 ; U5.21 54.413,40.964 57.828,37.549 C12.2 v1@56.407,36.703 ; v1(51.664,27.102) R16.2@51.664,28.575 ; R1.1 v1(75.748,81.28)
  Top Layer w0.5: U16.1 73.489,66.675 R2.1 ; R10.2 v1@79.705,50.749
  Top Layer w0.508: R21.2 v1(71.476,18.898)
  Top Layer w0.6: R17.2 v1(19.99,19.025) ; C8.2 v1(28.321,48.514) ; R18.2 v1(36.322,18.429) R4.2 ; R19.2 v1(49.309,21.75) ; R20.2 v1(54.889,18.898)
  Top Layer w0.762: C13.2 73.138,63.957 73.239,63.856
  Top Layer w0.8: C10.1@17.805,65.532 C4.2 ; J1.2@37.348,25.781 C5.2
  Top Layer w1: C21.1@73.239,61.697 v1(73.239,62.992) 73.239,63.856 U16.1@73.239,66.769
  Top Layer w1.2: C10.1@17.719,65.314 C10.1 17.653,59.617 J2.20 J2.19
  other v1: 56.269,22.155 57.285,22.155 56.388,36.703 79.756,50.749 73.293,64.897
VCC33: C22.1 C23.1 R28.1 R32.1 U4.16 U4.31 U4.35 U16.2 U16.4 | length 92.1
  Top Layer w0.3: U4.35 37.356,82.136 37.592,82.372 ; U4.31 39.356,82.231 39.497,82.372 ; U4.16 46.856,77.692 47.65,78.486 47.65,79.248
  Top Layer w0.305: 47.65,79.248 47.65,82.296
  Top Layer w0.508: v1(29.566,66.548) R32.1@29.566,68.072 ; R32.1@29.591,68.047 R28.1@31.115,68.047
  Top Layer w1.2: v1(32.264,78.892) 32.264,81.108 33.528,82.372 37.592,82.372 39.497,82.372 60.681,82.372 61.849,81.204 61.849,72.796 62.022,72.623 U16.4@70.993,72.623 ; U16.2@70.993,66.823 U16.2 U16.4@70.993,72.623 ; U16.4@71.247,72.623 U16.4@70.993,72.623
  Bottom Layer w0.508: v1(29.566,66.548) 29.566,78.08 30.378,78.892 v1(32.264,78.892)
VE: J2.2 J3.9 J3.10
VOUT1: C24.1 C25.1 U4.18 U4.19 | length 11.1
  Top Layer w0.305: U4.19@45.362,76.504 45.362,75.184 45.593,74.953 ; U4.18 45.856,75.225 45.593,74.962 45.593,74.953 ; C24.1 C25.1 46.784,69.543 46.784,71.882 45.593,73.073 45.593,74.953
VR: 
WR: 
X1: C16.1 U5.24 Y1.1 | length 13
  Top Layer w0.432: U5.24 55.378,43.364 Y1.1 C16.1@62.179,46.66
X2: C15.2 U5.23 Y1.2 | length 12.1
  Top Layer w0.432: U5.23 57.69,42.564 Y1.2 C15.2
X5-CS: U5.39 U7.1 | length 6.1
  Top Layer w0.432: U7.1 42.824,54.813 43.542,54.096 U5.39
X5-SCK: U5.36 U7.6 | length 12.6
  Top Layer w0.432: U7.6 45.464,61.724 47.752,59.436 47.752,56.261 45.942,54.451 U5.36
X5-SI: U5.35 U7.5 | length 12.6
  Top Layer w0.432: U5.35 46.742,54.235 48.717,56.21 48.717,59.868 46.784,61.801 U7.5
X5-SO: U5.38 U7.2 | length 5.9
  Top Layer w0.432: U7.2 44.144,55.588 44.342,55.391 U5.38
X5-WP: U5.37 U7.3 | length 6
  Top Layer w0.432: U5.37 45.142,55.226 45.464,55.548 U7.3
pads on no net: J1.3 U4.1 U4.2 U4.6 U4.7 U4.8 U4.9 U4.10 U4.11 U4.12 U4.13 U4.24 U4.30 U4.36 U4.37 U4.38 U5.1 U5.4 U5.18 U5.19 U5.33 U5.43 U5.62 U5.63 U5.64

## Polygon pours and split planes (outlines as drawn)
GND on Top Layer "BottomLayer-No Net" (hatched 90Degree grid 0.3 track 0.3, remove dead copper, pour order 11): 0,91.48 91.394,91.48 91.394,0.208 91.186,0 0.889,0 0,0.889
VCC on Top Layer "Top Layer-No Net 1" (hatched 90Degree grid 0.3 track 0.3, remove dead copper, pour order 16): 71.628,65.024 71.628,58.372 71.707,58.293 75.494,58.293 75.748,58.547 75.819,58.618 75.819,65.024
VCC33 on Top Layer "Top Layer-No Net 1" (hatched 90Degree grid 0.3 track 0.3, remove dead copper, pour order 15): 75.438,70.358 67.377,70.358 67.377,74.235 67.545,74.422 67.608,74.492 74.526,74.492 75.319,74.492 75.381,74.422
VCC on Top Layer "Top Layer-VCC" (hatched 90Degree grid 0.508 track 0.508, remove dead copper, pour order 12): -143.993,-140.749
+12V on Top Layer "Top Layer-+12V" (hatched 90Degree grid 0.508 track 0.508, remove dead copper, pour order 10): -143.993,-140.749
VCC on Top Layer "Top Layer-No Net" (hatched 90Degree grid 0.3 track 0.3, remove dead copper, pour order 13): 54.973,25.279 63.101,25.279 63.101,23.374 63.101,23.247 64.752,23.247 64.752,21.342 55.1,21.342 54.973,21.469
+12V on Top Layer "Top Layer-No Net" (hatched 90Degree grid 0.3 track 0.3, remove dead copper, pour order 14): 76.309,25.406 76.309,21.342 76.309,21.215 66.022,21.215 66.022,23.374 67.546,23.374 67.546,25.406
GND on Bottom Layer "BottomLayer-No Net" (hatched 90Degree grid 0.3 track 0.3, remove dead copper, pour order 13): 0.508,91.567 91.186,91.567 91.694,91.059 91.694,1.016 90.678,0 0.762,0 0.254,0.508
+12V on PWR (split plane): 23.243,32.108 16.66,25.525 8.382,25.525 8.317,25.517 8.256,25.491 8.204,25.451 8.164,25.399 8.138,25.338 8.13,25.273 8.13,16.002 8.138,15.937 8.164,15.876 8.204,15.824 13.03,10.998 13.082,10.958 13.143,10.932 13.208,10.924 78.74,10.924 78.805,10.932 78.866,10.958 78.918,10.998 82.982,15.062 83.022,15.114 83.048,15.175 83.056,15.24 83.056,22.352 83.048,22.417 83.022,22.478 82.982,22.53 82.93,22.57 82.869,22.596 82.804,22.604 69.975,22.604 69.975,37.975 79.123,37.975 79.123,35.56 79.131,35.495 79.157,35.434 79.197,35.382 79.249,35.342 79.31,35.316 79.375,35.308 87.124,35.308 87.124,16.233 75.207,4.316 59.286,4.316 54.661,8.941 54.609,8.981 54.548,9.007 54.483,9.015 32.639,9.015 32.574,9.007 32.513,8.981 32.461,8.941 27.836,4.316 17.122,4.316 5.713,15.725 5.713,27.815 11.811,27.815 11.876,27.823 11.937,27.849 11.989,27.889 17.503,33.403 20.955,33.403 21.02,33.411 21.081,33.437 21.133,33.477 21.173,33.529 21.199,33.59 21.207,33.655 21.207,36.957 21.199,37.022 21.173,37.083 21.133,37.135 21.006,37.262 20.954,37.302 20.893,37.328 20.828,37.336 14.476,37.336 14.476,40.515 23.243,40.515
-12V on PWR (split plane): 25.783,30.076 19.073,23.366 11.176,23.366 11.111,23.358 11.05,23.332 10.998,23.292 10.958,23.24 10.932,23.179 10.924,23.114 10.924,16.383 10.932,16.318 10.958,16.257 10.998,16.205 13.03,14.173 13.082,14.133 13.143,14.107 13.208,14.099 77.597,14.099 77.662,14.107 77.723,14.133 77.775,14.173 79.807,16.205 79.847,16.257 79.873,16.318 79.881,16.383 79.881,19.812 79.873,19.877 79.847,19.938 79.807,19.99 79.755,20.03 79.694,20.056 79.629,20.064 68.197,20.064 68.197,41.785 79.123,41.785 79.123,38.479 69.723,38.479 69.658,38.471 69.597,38.445 69.545,38.405 69.505,38.353 69.479,38.292 69.471,38.227 69.471,22.352 69.479,22.287 69.505,22.226 69.545,22.174 69.597,22.134 69.658,22.108 69.723,22.1 82.552,22.1 82.552,15.344 78.636,11.428 13.312,11.428 8.634,16.106 8.634,25.021 16.764,25.021 16.829,25.029 16.89,25.055 16.942,25.095 23.673,31.826 23.713,31.878 23.739,31.939 23.747,32.004 23.747,40.767 23.739,40.832 23.713,40.893 23.673,40.945 23.621,40.985 23.56,41.011 23.495,41.019 14.476,41.019 14.476,44.325 25.783,44.325
no net on PWR (split plane): 90.947,0.552 76.981,0.552 90.947,14.517
VCC on PWR (split plane): 90.947,40.003 83.924,40.003 82.929,40.998 82.929,45.847 82.921,45.912 82.895,45.973 82.855,46.025 82.803,46.065 82.742,46.091 82.677,46.099 70.358,46.099 70.293,46.091 70.232,46.065 70.18,46.025 70.14,45.973 70.114,45.912 70.106,45.847 70.106,42.289 67.945,42.289 67.88,42.281 67.819,42.255 67.767,42.215 67.727,42.163 67.701,42.102 67.693,42.037 67.693,19.812 67.701,19.747 67.727,19.686 67.767,19.634 67.819,19.594 67.88,19.568 67.945,19.56 79.377,19.56 79.377,16.487 77.493,14.603 13.312,14.603 11.428,16.487 11.428,22.862 19.177,22.862 19.242,22.87 19.303,22.896 19.355,22.936 26.213,29.794 26.253,29.846 26.279,29.907 26.287,29.972 26.287,44.577 26.279,44.642 26.253,44.703 26.213,44.755 26.161,44.795 26.1,44.821 26.035,44.829 14.224,44.829 14.159,44.821 14.098,44.795 14.046,44.755 14.006,44.703 13.98,44.642 13.972,44.577 13.972,40.767 13.972,35.868 9.471,31.367 0.491,31.367 0.491,91.122 90.947,91.122
no net on PWR (split plane): 14.586,0.552 0.491,0.552 0.491,14.646
+24V on PWR (split plane): 82.425,40.894 82.433,40.829 82.459,40.768 82.499,40.716 83.642,39.573 83.694,39.533 83.755,39.507 83.82,39.499 90.947,39.499 90.947,15.231 76.268,0.552 15.299,0.552 0.491,15.36 0.491,30.863 9.576,30.863 9.641,30.871 9.702,30.897 9.754,30.937 14.402,35.585 14.442,35.637 14.468,35.698 14.476,35.763 14.476,36.832 20.703,36.832 20.703,33.907 17.399,33.907 17.334,33.899 17.273,33.873 17.221,33.833 11.707,28.319 5.461,28.319 5.396,28.311 5.335,28.285 5.283,28.245 5.243,28.193 5.217,28.132 5.209,28.067 5.209,15.621 5.217,15.556 5.243,15.495 5.283,15.443 16.84,3.886 16.892,3.846 16.953,3.82 17.018,3.812 27.94,3.812 28.005,3.82 28.066,3.846 28.118,3.886 32.743,8.511 54.379,8.511 59.004,3.886 59.056,3.846 59.117,3.82 59.182,3.812 75.311,3.812 75.376,3.82 75.437,3.846 75.489,3.886 87.554,15.951 87.572,15.973 87.594,16.003 87.62,16.064 87.628,16.129 87.628,35.56 87.62,35.625 87.594,35.686 87.554,35.738 87.502,35.778 87.441,35.804 87.376,35.812 79.627,35.812 79.627,42.037 79.619,42.102 79.593,42.163 79.553,42.215 79.501,42.255 79.44,42.281 79.375,42.289 70.61,42.289 70.61,45.595 82.425,45.595
no net on GND (split plane): 14.586,0.552 0.491,0.552 0.491,14.646
no net on GND (split plane): 90.947,0.552 77.108,0.552 90.947,14.39
GND on GND (split plane): 90.947,40.003 83.924,40.003 82.929,40.998 82.929,46.863 82.921,46.928 82.895,46.989 82.855,47.041 82.803,47.081 82.742,47.107 82.677,47.115 70.358,47.115 70.293,47.107 70.232,47.081 70.18,47.041 70.14,46.989 70.114,46.928 70.106,46.863 70.106,42.037 70.114,41.972 70.14,41.911 70.18,41.859 70.232,41.819 70.293,41.793 70.358,41.785 79.123,41.785 79.123,35.56 79.131,35.495 79.157,35.434 79.197,35.382 79.249,35.342 79.31,35.316 79.375,35.308 87.251,35.308 87.251,16.487 79.779,9.015 33.02,9.015 32.955,9.007 32.894,8.981 32.842,8.941 28.09,4.189 17.122,4.189 5.586,15.725 5.586,27.561 11.811,27.561 11.876,27.569 11.937,27.595 11.989,27.635 17.757,33.403 20.828,33.403 20.893,33.411 20.954,33.437 21.006,33.477 21.046,33.529 21.072,33.59 21.08,33.655 21.08,36.957 21.072,37.022 21.046,37.083 21.006,37.135 20.954,37.175 20.893,37.201 20.828,37.209 15.494,37.209 15.429,37.201 15.368,37.175 15.316,37.135 9.421,31.24 0.491,31.24 0.491,91.122 90.947,91.122
VE on GND (split plane): 82.425,40.894 82.433,40.829 82.459,40.768 82.499,40.716 83.642,39.573 83.694,39.533 83.755,39.507 83.82,39.499 90.947,39.499 90.947,15.104 76.395,0.552 15.299,0.552 0.491,15.36 0.491,30.736 9.525,30.736 9.59,30.744 9.651,30.77 9.703,30.81 15.598,36.705 20.576,36.705 20.576,33.907 17.653,33.907 17.588,33.899 17.527,33.873 17.475,33.833 11.707,28.065 5.334,28.065 5.269,28.057 5.208,28.031 5.156,27.991 5.116,27.939 5.09,27.878 5.082,27.813 5.082,15.621 5.09,15.556 5.116,15.495 5.156,15.443 16.84,3.759 16.862,3.741 16.892,3.719 16.953,3.693 17.018,3.685 28.194,3.685 28.259,3.693 28.32,3.719 28.372,3.759 33.124,8.511 79.883,8.511 79.948,8.519 80.009,8.545 80.061,8.585 87.681,16.205 87.721,16.257 87.747,16.318 87.755,16.383 87.755,35.56 87.747,35.625 87.721,35.686 87.681,35.738 87.629,35.778 87.568,35.804 87.503,35.812 79.627,35.812 79.627,42.037 79.619,42.102 79.593,42.163 79.553,42.215 79.501,42.255 79.44,42.281 79.375,42.289 70.61,42.289 70.61,46.611 82.425,46.611

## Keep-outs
Keep-Out Layer:
  circle w0.127: c4.624,76.73 r1.8
  circle w0.127: c21.694,6.18 r1.5
  circle w0.127: c69.719,6.18 r1.5
  circle w0.127: c86.869,76.705 r1.8
  circle w0.127: c45.719,2.48 r1.8
  circle w0.127: c79.519,81.58 r1.25
  circle w0.127: c11.419,81.555 r1.25
  circle w0.127: c79.619,36.455 r1.25
  circle w0.127: c11.544,36.53 r1.25
  lines w0.102: 0.044,11.43 0.054,80.205 ; 11.369,0.119 80.069,0.13 ; 91.366,11.455 91.369,80.155
  lines w0.127: 0.044,11.405 ccw(c2.444,11.405) 2.444,9.005 ; 0.069,80.155 cw(c2.469,80.155) 2.469,82.555 ; 2.479,8.996 cw(c2.479,2.496) 8.979,2.496 ; 2.479,82.557 ccw(c2.479,89.057) 8.979,89.057 ; 8.969,2.505 ccw(c11.369,2.505) 11.369,0.105 ; 8.994,89.08 cw(c11.394,89.08) 11.394,91.48 ; 80.069,0.13 ccw(c80.069,2.53) 82.469,2.53 ; 80.069,91.48 cw(c80.069,89.08) 82.469,89.08 ; 82.466,2.496 cw(c88.966,2.496) 88.966,8.996 ; 82.466,89.057 ccw(c88.966,89.057) 88.966,82.557 ; 88.969,9.005 ccw(c88.969,11.405) 91.369,11.405 ; 88.994,82.555 cw(c88.994,80.155) 91.394,80.155
  lines w0.305: 11.394,91.48 29.439,91.48 34.377,91.48 35.281,90.576 37.414,90.576 56.439,90.576 57.342,91.48 80.144,91.48

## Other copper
Top Layer:
  pour cut-out: 77.216,25.96 77.165,25.909 77.165,20.351 54.563,20.351 54.046,20.869 54.046,25.96
PWR (plane layer: these items are gaps in the copper):
  lines w0.5: 14.224,37.084 20.828,37.084 20.955,36.957 20.955,33.655 17.399,33.655 11.811,28.067 5.461,28.067 5.461,15.621 17.018,4.064 27.94,4.064 32.639,8.763 54.483,8.763 59.182,4.064 75.311,4.064 87.376,16.129 87.376,35.56 79.375,35.56 79.375,42.037 70.358,42.037 ; 79.375,38.227 69.723,38.227 69.723,22.352 82.804,22.352 82.804,15.24 78.74,11.176 13.208,11.176 8.382,16.002 8.382,25.273 16.764,25.273 23.495,32.004 23.495,40.767 14.224,40.767 ; 14.224,40.767 14.224,44.577 26.035,44.577 26.035,29.972 19.177,23.114 11.176,23.114 11.176,16.383 13.208,14.351 77.597,14.351 79.629,16.383 79.629,19.812 67.945,19.812 67.945,42.037 70.358,42.037 ; 14.224,40.767 14.224,35.763 9.576,31.115 0.107,31.115 0.107,15.387 15.494,0 76.073,0 91.367,15.294 91.367,39.751 83.82,39.751 82.677,40.894 82.677,45.847 70.358,45.847 70.358,42.037
GND (plane layer: these items are gaps in the copper):
  lines w0.5: -0.02,15.514 -0.02,30.988 9.525,30.988 15.494,36.957 20.828,36.957 20.828,33.655 17.653,33.655 11.811,27.813 5.334,27.813 5.334,15.621 17.018,3.937 28.194,3.937 33.02,8.763 79.883,8.763 87.503,16.383 87.503,35.56 79.375,35.56 79.375,42.037 70.358,42.037 70.358,46.863 82.677,46.863 82.677,40.894 83.82,39.751 91.457,39.751 91.457,15.257 76.241,0.041 15.453,0.041 -0.02,15.514

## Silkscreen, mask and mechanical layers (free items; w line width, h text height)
Top Overlay:
  text "Sanpell_CPU_V5.2" at 33.782,86.614 h1.98
  text "K" at 20.701,80.899 h1.52
  text "A" at 69.596,80.772 h1.52
Mechanical 1:
  lines w0.2: -3.048,43.561 94.488,43.561 ; -2.794,63.906 94.463,63.906 ; 5.715,-3.048 5.715,94.922 ; 84.912,-1.524 84.912,94.818
  lines w0.254: 14.605,16.789 95.275,16.789 ; 21.717,81.28 69.977,81.28

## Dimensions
-0.02,0.041 to -0.02,91.632 on Mechanical 1
2.952,0.117 to 14.58,16.789 on Mechanical 1
-0.019,12.369 to 13.653,14.63 on Mechanical 1
13.647,12.369 to 29.681,14.732 on Mechanical 1
29.674,12.471 to 45.708,14.834 on Mechanical 1
45.727,12.547 to 61.761,14.91 on Mechanical 1
61.754,12.7 to 77.788,15.062 on Mechanical 1
-0.02,0.041 to 91.457,0.041 on Mechanical 1
-0.02,-2.286 to 5.715,-2.921 on Mechanical 1
84.912,-1.524 to 91.457,-1.397 on Mechanical 1
-0.02,0.041 to -2.921,43.561 on Mechanical 1
-5.105,43.586 to -2.692,63.906 on Mechanical 1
